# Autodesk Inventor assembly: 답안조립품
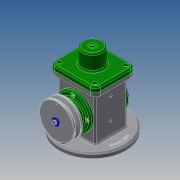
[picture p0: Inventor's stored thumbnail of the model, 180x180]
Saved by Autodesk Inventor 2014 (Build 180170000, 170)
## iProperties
Created: 2019-08
Part Number: 답안조립품
Document SubType Name: Assembly
Designer: kb542-17
Author: kb542-17
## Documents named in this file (18)
- C:\Users\kb542-17\Desktop\490804V1022\답안조립품.iam
- C:\Users\kb542-17\Desktop\490804V1022\본체.ipt
- C:\Users\kb542-17\Desktop\490804V1022\E-링.ipt
- C:\Users\kb542-17\Desktop\490804V1022\V-벨트풀리.ipt
- C:\Users\kb542-17\Desktop\490804V1022\덮개.ipt
- C:\Users\kb542-17\Desktop\490804V1022\뒤커버.ipt
- C:\Users\kb542-17\Desktop\490804V1022\링크.ipt
- C:\Users\kb542-17\Desktop\490804V1022\베어링 17 x 40 x 12.ipt
- C:\Users\kb542-17\Desktop\490804V1022\볼트 M4 x 8.ipt
- C:\Users\kb542-17\Desktop\490804V1022\볼트 M4 x 10.ipt
- C:\Users\kb542-17\Desktop\490804V1022\슬라이더.ipt
- C:\Users\kb542-17\Desktop\490804V1022\앞커버.ipt
- C:\Users\kb542-17\Desktop\490804V1022\오일 실 17 30 8.ipt
- C:\Users\kb542-17\Desktop\490804V1022\와셔 4x16.ipt
- C:\Users\kb542-17\Desktop\490804V1022\클레비스 핀 6 x 22.ipt
- 클레비스 핀 6 x 22.ipt
- C:\Users\kb542-17\Desktop\490804V1022\키 4 x 4 x 12.ipt
- C:\Users\kb542-17\Desktop\490804V1022\편심축.ipt
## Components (2 placed, 2 different names)
1. E-링:1
2. V-벨트풀리:1
